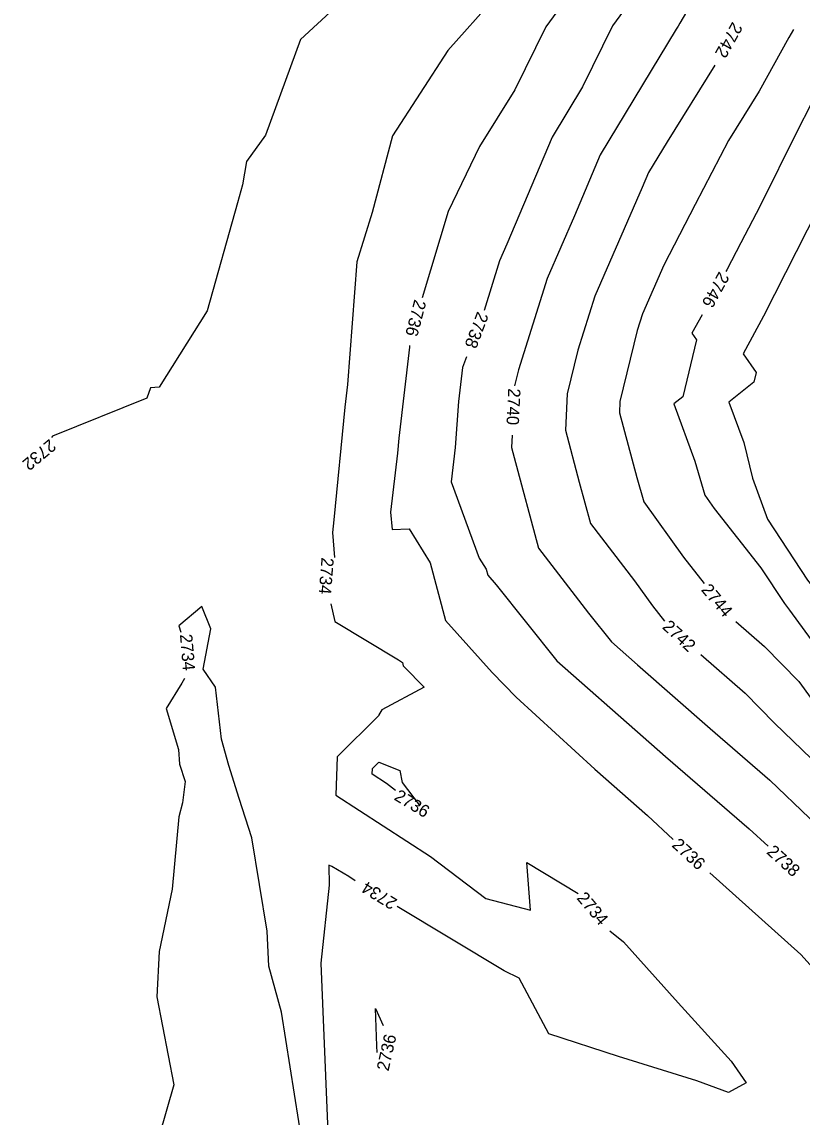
# Model space of a CAD drawing. Extents: x 1326424 to 1329294, y 1001359 to 1003823.
# Drawn here: x 1327992 to 1328118.1, y 1002300.7 to 1002477.9 of the extents above; entities that cross this region are included whole.
import ezdxf

# ---------------------------------------------------------------- set-up
doc = ezdxf.new("R2010")
doc.units = 0
doc.layers.add('Prop Rem of Exist Asph Pvmt', color=7, linetype='Continuous')
doc.layers.add('Scratch_Level_3', color=7, linetype='Continuous')

msp = doc.modelspace()

# ---------------------------------------------------------------- linework, layer by layer
at = {"layer": 'Prop Rem of Exist Asph Pvmt'}
for points in [[(1328115, 1002508.65), (1328109.88, 1002497.34), (1328098.38, 1002477.7), (1328098.09, 1002477.19), (1328097.78, 1002476.69), (1328085.49, 1002456.36), (1328081.34, 1002446.53), (1328076.91, 1002436.36), (1328072.26, 1002421.62), (1328071.63, 1002419.02)], [(1328071.23, 1002411.03), (1328071.14, 1002409.01), (1328071.56, 1002407.4), (1328075.52, 1002392.73), (1328083.6, 1002382.25), (1328087.3, 1002377.58), (1328091.49, 1002373.9), (1328103.25, 1002363.6), (1328112.91, 1002355.24), (1328119.31, 1002349.05), (1328121.34, 1002346.97), (1328131.26, 1002336.5), (1328132.46, 1002335.28)]]:
    msp.add_lwpolyline(points, dxfattribs=at)
at = {"layer": 'Scratch_Level_3'}
for points in [[(1328152.85, 1002525.48), (1328147.64, 1002513.47), (1328147.38, 1002512.95), (1328142.9, 1002503.77), (1328134.32, 1002487.55), (1328128.5, 1002480.3), (1328124.46, 1002473.13), (1328119.53, 1002464.51), (1328117.35, 1002460.22), (1328111.34, 1002448.11), (1328108.2, 1002442.13), (1328105.95, 1002437.78), (1328105.8, 1002437.49)], [(1328101.87, 1002521.58), (1328101.49, 1002518.88), (1328099.63, 1002513.96), (1328093.94, 1002502.01), (1328089.71, 1002494.95), (1328076.67, 1002477.07), (1328071.68, 1002466.9), (1328065.96, 1002457.72), (1328060.89, 1002447.21), (1328056.67, 1002433.23)], [(1328110.58, 1002520.46), (1328109.7, 1002518.05), (1328109.48, 1002516.5), (1328105.75, 1002506.63), (1328104.43, 1002503.7), (1328102.3, 1002500.07), (1328093.85, 1002486), (1328087.46, 1002477.23), (1328082.64, 1002467.4), (1328077.69, 1002459.22), (1328070.4, 1002441.93), (1328069.22, 1002439.21), (1328066.69, 1002431.21)], [(1328051.41, 1002487.11), (1328045.27, 1002482.72), (1328037.03, 1002475.04), (1328031.38, 1002459.54), (1328028.28, 1002455.31), (1328027.64, 1002451.52), (1328026.83, 1002448.63), (1328021.91, 1002431.16), (1328014.18, 1002418.82), (1328012.77, 1002418.67), (1328012.16, 1002417.03), (1327996.91, 1002410.86), (1327996.75, 1002410.64)], [(1328070.12, 1002484.19), (1328068.44, 1002481.84), (1328060.84, 1002473.24), (1328051.89, 1002459.44), (1328048.6, 1002447.07), (1328046.12, 1002439.08), (1328044.61, 1002419.25), (1328044.18, 1002415.57), (1328042.43, 1002397.32), (1328042.19, 1002395.26), (1328042.51, 1002391.25)], [(1328116.73, 1002476.66), (1328115.99, 1002475.35), (1328111.19, 1002466.66), (1328106.24, 1002458.68), (1328100.81, 1002448.37), (1328095.75, 1002438.54), (1328092.31, 1002430.65), (1328091.47, 1002427.98), (1328088.67, 1002416.48), (1328088.58, 1002414.66), (1328091.38, 1002404.18), (1328092.53, 1002400.25), (1328098.94, 1002391.29), (1328102.3, 1002387.01)], [(1328104.02, 1002470.91), (1328096.28, 1002458.46), (1328093.29, 1002453.51), (1328092.28, 1002451.12), (1328084.61, 1002433.5), (1328081.87, 1002424.8), (1328080.15, 1002417.74), (1328079.86, 1002411.84), (1328082.1, 1002403.43), (1328083.91, 1002396.72), (1328091.05, 1002387.45), (1328093.95, 1002383.4), (1328095.87, 1002380.95)], [(1328122.4, 1002451.05), (1328120.74, 1002447.71), (1328111.91, 1002430.27), (1328108.58, 1002424.19), (1328110.68, 1002421.18), (1328110.3, 1002419.62), (1328106.3, 1002416.38), (1328108.69, 1002409.83), (1328110.12, 1002404.06), (1328112.53, 1002397.46), (1328119.02, 1002387.57), (1328124.88, 1002380.11), (1328129.38, 1002373.9), (1328130.83, 1002372.4), (1328134.65, 1002368.79), (1328136.64, 1002366.42)], [(1328101.94, 1002430.48), (1328100.32, 1002427.53), (1328101.07, 1002426.45), (1328098.83, 1002417.24), (1328097.4, 1002416.08), (1328100.78, 1002406.82), (1328102.4, 1002401.32), (1328103.93, 1002399.18), (1328111.46, 1002389.59), (1328115.26, 1002383.81), (1328116.09, 1002382.74), (1328125.71, 1002369.49), (1328128.81, 1002366.29), (1328136.96, 1002358.58), (1328138.43, 1002356.83), (1328145.34, 1002348.31)], [(1328054.65, 1002425.51), (1328054.62, 1002425.26), (1328052.91, 1002410.52), (1328052.68, 1002408.11), (1328051.59, 1002398.56), (1328051.82, 1002395.76), (1328054.61, 1002395.88), (1328057.97, 1002390.39), (1328060.47, 1002381.03), (1328068.01, 1002372.64), (1328071.87, 1002368.66), (1328084.62, 1002356.98), (1328093.13, 1002349.49), (1328097.3, 1002345.62)], [(1328063.86, 1002423.72), (1328063.19, 1002421.96), (1328062.57, 1002416.49), (1328062.04, 1002409.01), (1328061.37, 1002403.5), (1328065.93, 1002391.15), (1328067.04, 1002389.33), (1328067.3, 1002388.36), (1328068.67, 1002386.83), (1328078.44, 1002374.53), (1328092.44, 1002362.21), (1328096.04, 1002359.06), (1328109.56, 1002347.36), (1328112.62, 1002344.52)], [(1328038.25, 1002292), (1328037.67, 1002293.4), (1328037.47, 1002295.57), (1328033.95, 1002317.68), (1328031.88, 1002325.13), (1328031.6, 1002330.77), (1328029.13, 1002345.9), (1328027.08, 1002352.28), (1328025.42, 1002357.58), (1328024.26, 1002361.84), (1328023.28, 1002370.25), (1328021.29, 1002373.16), (1328022.53, 1002379.7), (1328021.04, 1002383.34), (1328017.34, 1002380.21), (1328017.65, 1002379.16)], [(1328041.92, 1002383.75), (1328042.57, 1002380.88), (1328052.86, 1002374.71), (1328053.49, 1002374.26), (1328053.64, 1002373.71), (1328053.78, 1002373.56), (1328056.99, 1002370.24), (1328050.18, 1002366.58), (1328049.7, 1002365.8), (1328049.69, 1002365.67), (1328042.95, 1002359.02), (1328042.74, 1002352.81), (1328058.03, 1002342.85), (1328066.99, 1002336.06), (1328074.22, 1002334.17), (1328073.6, 1002341.88), (1328081.94, 1002336.89)], [(1328107.41, 1002380.88), (1328112.04, 1002376.86), (1328117.6, 1002371.2), (1328122.04, 1002365.07), (1328126.79, 1002360.17), (1328130.9, 1002356.28), (1328141.56, 1002345.31), (1328146.05, 1002339.77), (1328150.61, 1002335.04), (1328151.02, 1002334.56), (1328164.39, 1002320.07), (1328168.92, 1002314.73), (1328174.24, 1002306.81)], [(1328101.73, 1002375.53), (1328108.93, 1002369.28), (1328113.67, 1002364.45), (1328119.66, 1002358.66), (1328124.4, 1002353.81), (1328126.95, 1002351.12), (1328144.19, 1002333.55), (1328144.75, 1002332.9), (1328146.24, 1002331.1), (1328163.14, 1002311.16), (1328164.28, 1002309.78), (1328165.85, 1002306.56), (1328169.07, 1002302.03)], [(1328018.28, 1002371.69), (1328017.82, 1002370.89), (1328015.31, 1002366.8), (1328017.31, 1002360.17), (1328017.46, 1002357.82), (1328018.34, 1002355.03), (1328017.92, 1002351.54), (1328017.34, 1002349.27), (1328016.26, 1002337.61), (1328014.14, 1002327.52), (1328013.8, 1002320.18), (1328016.51, 1002305.91), (1328011.79, 1002289.45), (1328011.39, 1002289.33), (1327997.67, 1002283.83)], [(1328048.61, 1002356.17), (1328048.65, 1002357.11), (1328049.68, 1002358.13), (1328053.1, 1002356.78), (1328053.47, 1002354.82), (1328056.22, 1002351.25)], [(1328052.37, 1002353.57), (1328050.93, 1002354.66), (1328048.61, 1002356.17)], [(1328045.84, 1002338.95), (1328044.82, 1002339.62), (1328042.08, 1002341.26), (1328041.62, 1002341.46), (1328041.67, 1002338.23), (1328040.3, 1002325.63), (1328040.55, 1002319.08), (1328041.53, 1002295.71), (1328042.83, 1002295.86), (1328042.04, 1002293.99), (1328041.42, 1002291.71), (1328042.85, 1002274.08), (1328043.01, 1002273.28), (1328042.95, 1002272.71), (1328043.47, 1002266.42), (1328042.23, 1002272.67), (1328042.03, 1002273.98), (1328040.07, 1002284.24)], [(1328103.19, 1002340.21), (1328117.91, 1002327), (1328119.9, 1002324.79), (1328124.54, 1002320.74), (1328125.71, 1002319.32), (1328131.13, 1002313.12), (1328136.44, 1002302.08), (1328142.7, 1002294.95), (1328143.13, 1002292.48), (1328143.43, 1002290.69), (1328140.12, 1002288.67), (1328135.22, 1002286.79), (1328125.42, 1002272.5), (1328124.76, 1002272.39), (1328121.43, 1002269.71), (1328118.86, 1002267.26)], [(1328087.04, 1002330.84), (1328089.27, 1002329.05), (1328098.09, 1002319.22), (1328106.65, 1002309.78), (1328109.09, 1002306.24), (1328106.25, 1002304.71), (1328101.13, 1002306.56), (1328088.46, 1002310.51), (1328077.16, 1002314.19), (1328072.39, 1002323.17), (1328069.96, 1002324.39), (1328052.67, 1002334.79)], [(1328049.35, 1002312.23), (1328049.12, 1002318.27), (1328050.37, 1002315.52)], [(1328049.39, 1002311.16), (1328049.35, 1002312.23)]]:
    msp.add_lwpolyline(points, dxfattribs=at)

# ---------------------------------------------------------------- texts
at = {"layer": 'Prop Rem of Exist Asph Pvmt'}
msp.add_text('2740', height=2, rotation=267.1542, dxfattribs=at).set_placement((1328070.61, 1002418.65))
at = {"layer": 'Scratch_Level_3'}
for s, rotation, p in [('2742', 240.6801, (1328106.88, 1002478)), ('2746', 241.2172, (1328104.72, 1002437.61)), ('2736', 255.3491, (1328055.45, 1002433.08)), ('2738', 249.304, (1328065.62, 1002431.13)), ('2732', 219.8338, (1327996.43, 1002410.5)), ('2734', 265.4474, (1328040.42, 1002391.29)), ('2744', 309.83, (1328101.71, 1002385.97)), ('2742', 317.2168, (1328095.4, 1002379.86)), ('2734', 274.7693, (1328017.51, 1002378.78)), ('2736', 328.9298, (1328052.01, 1002352.13)), ('2736', 317.4255, (1328096.94, 1002344.57)), ('2738', 317.6426, (1328112.26, 1002343.45)), ('2734', 148.6354, (1328052.8, 1002335.85)), ('2734', 310.1342, (1328081.58, 1002336.1)), ('2736', 77.3369, (1328051.24, 1002308.05))]:
    msp.add_text(s, height=2, rotation=rotation, dxfattribs=at).set_placement(p)

doc.saveas('drawing.dxf')
